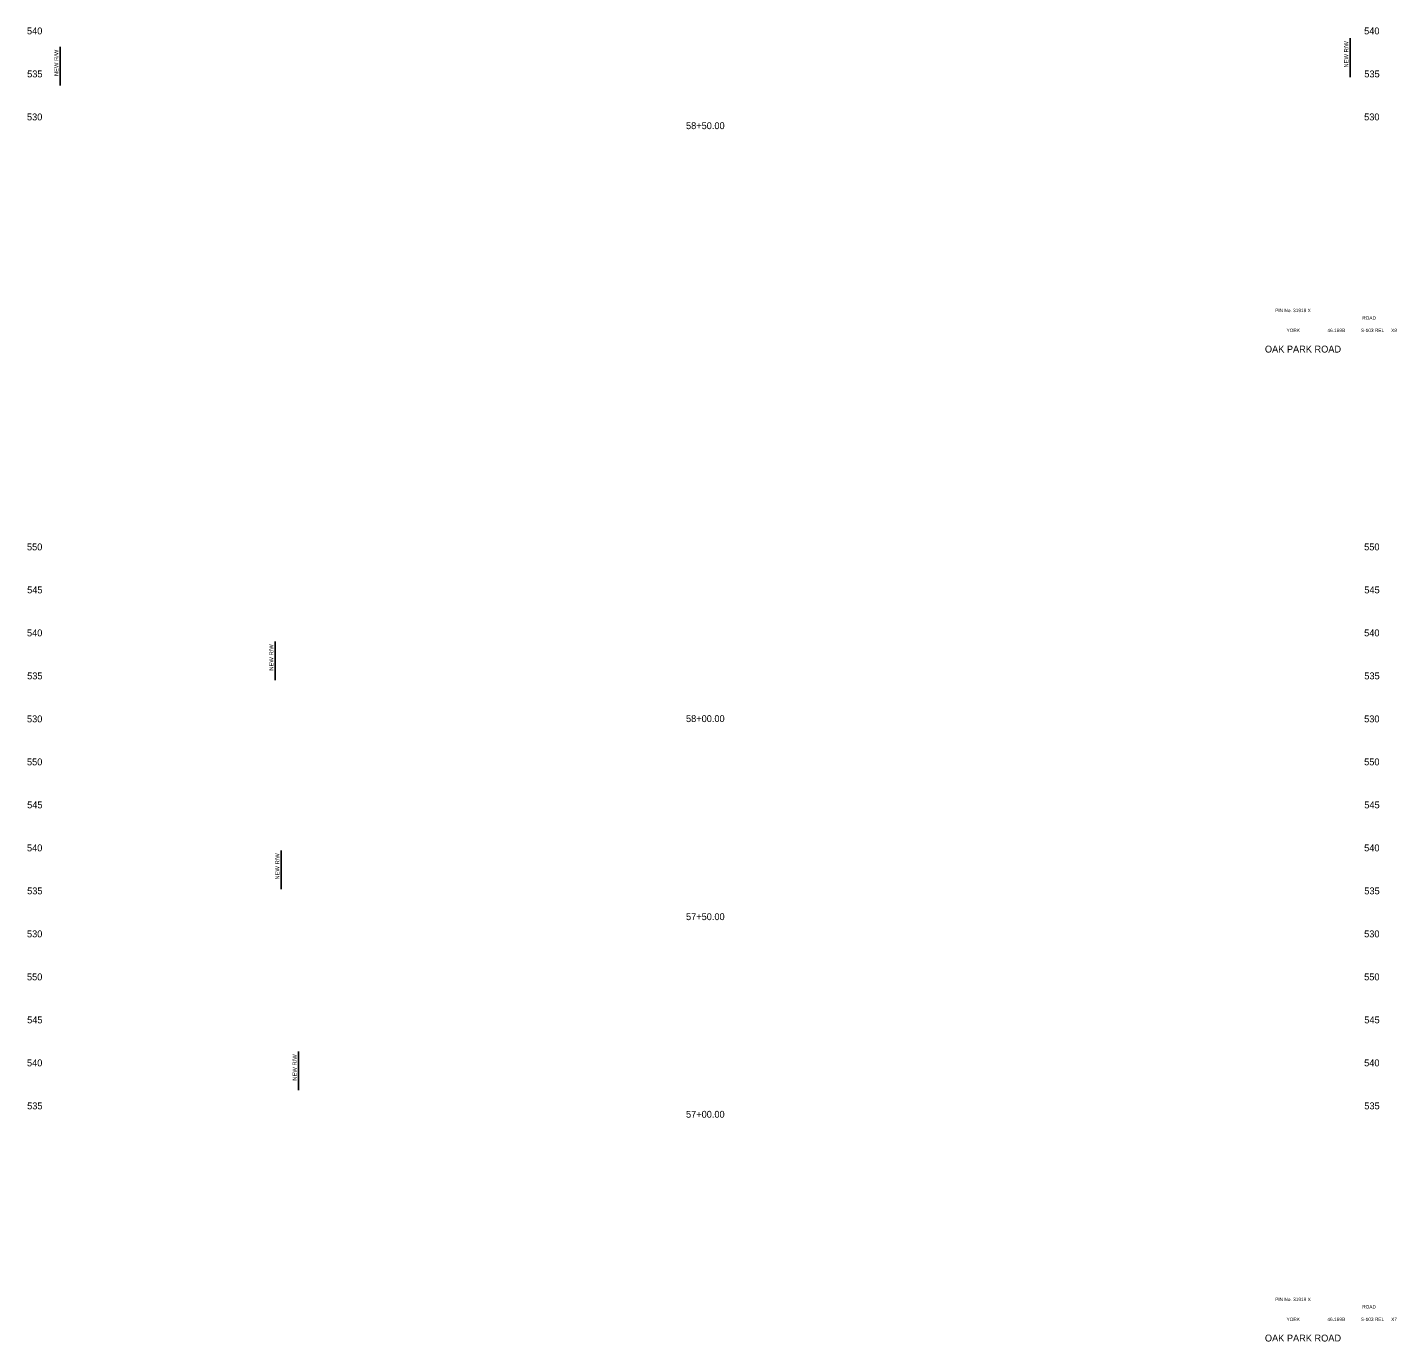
# Model space of a CAD drawing. Extents: x 1001 to 1161, y 1005 to 3518.
# Drawn here: x 1001.2 to 1160.4, y 1788.1 to 1940.9 of the extents above; entities that cross this region are included whole.
import ezdxf

# ---------------------------------------------------------------- set-up
doc = ezdxf.new("R2010")
doc.units = 0
for name, color, linetype in [('RD_SHT_TX', 7, 'Continuous'), ('RD_XS_NewRW', 7, 'Continuous'), ('RD_XS_TX_Elev_EX', 7, 'Continuous'), ('RD_XS_TX_Station', 7, 'Continuous')]:
    doc.layers.add(name, color=color, linetype=linetype)

msp = doc.modelspace()

# ---------------------------------------------------------------- linework, layer by layer
at = {"layer": 'RD_XS_NewRW'}
for p, q in [((1155, 1939.64), (1155, 1935.14)), ((1005, 1938.65), (1005, 1934.15)), ((1030, 1869.51), (1030, 1865.01)), ((1030.69, 1845.2), (1030.69, 1840.7)), ((1032.72, 1821.83), (1032.72, 1817.33))]:
    msp.add_line(p, q, dxfattribs=at)

# ---------------------------------------------------------------- texts
at = {"layer": 'RD_SHT_TX'}
for s, height, p in [('PIN No. 31919 X', 0.4, (1146.29, 1907.8)), ('ROAD', 0.4, (1156.41, 1906.93)), ('YORK', 0.4, (1147.61, 1905.48)), ('46.169B', 0.4, (1152.37, 1905.48)), ('S-103 REL', 0.4, (1156.26, 1905.48)), ('X8', 0.4, (1159.78, 1905.48)), ('OAK PARK ROAD', 0.8, (1145.1, 1903.1)), ('PIN No. 31919 X', 0.4, (1146.29, 1792.8)), ('ROAD', 0.4, (1156.41, 1791.93)), ('YORK', 0.4, (1147.61, 1790.48)), ('46.169B', 0.4, (1152.37, 1790.48)), ('S-103 REL', 0.4, (1156.26, 1790.48)), ('X7', 0.4, (1159.78, 1790.48)), ('OAK PARK ROAD', 0.8, (1145.1, 1788.1))]:
    msp.add_text(s, height=height, dxfattribs=at).set_placement(p)
at = {"layer": 'RD_XS_NewRW'}
for p in [(1004.8, 1935.25), (1154.8, 1936.24), (1029.8, 1866.11), (1030.49, 1841.81), (1032.52, 1818.43)]:
    msp.add_text('NEW R/W ', height=0.488, rotation=90, dxfattribs=at).set_placement(p)
at = {"layer": 'RD_XS_TX_Elev_EX'}
for s, p in [('540', (1001.14, 1940.1)), ('540', (1156.64, 1940.1)), ('535', (1001.16, 1935.1)), ('535', (1156.66, 1935.1)), ('530', (1001.14, 1930.1)), ('530', (1156.64, 1930.1)), ('550', (1001.14, 1880.1)), ('550', (1156.64, 1880.1)), ('545', (1001.16, 1875.1)), ('545', (1156.66, 1875.1)), ('540', (1001.14, 1870.1)), ('540', (1156.64, 1870.1)), ('535', (1001.16, 1865.1)), ('535', (1156.66, 1865.1)), ('530', (1001.14, 1860.1)), ('530', (1156.64, 1860.1)), ('550', (1001.14, 1855.1)), ('550', (1156.64, 1855.1)), ('545', (1001.16, 1850.1)), ('545', (1156.66, 1850.1)), ('540', (1001.14, 1845.1)), ('540', (1156.64, 1845.1)), ('535', (1001.16, 1840.1)), ('535', (1156.66, 1840.1)), ('530', (1001.14, 1835.1)), ('530', (1156.64, 1835.1)), ('550', (1001.14, 1830.1)), ('550', (1156.64, 1830.1)), ('545', (1001.16, 1825.1)), ('545', (1156.66, 1825.1)), ('540', (1001.14, 1820.1)), ('540', (1156.64, 1820.1)), ('535', (1001.16, 1815.1)), ('535', (1156.66, 1815.1))]:
    msp.add_text(s, height=0.8, dxfattribs=at).set_placement(p)
at = {"layer": 'RD_XS_TX_Station'}
for s, p in [('58+50.00', (1077.78, 1929.08)), ('58+00.00', (1077.78, 1860.13)), ('57+50.00', (1077.78, 1837.1)), ('57+00.00', (1077.78, 1814.12))]:
    msp.add_text(s, height=0.8, dxfattribs=at).set_placement(p)

doc.saveas('drawing.dxf')
